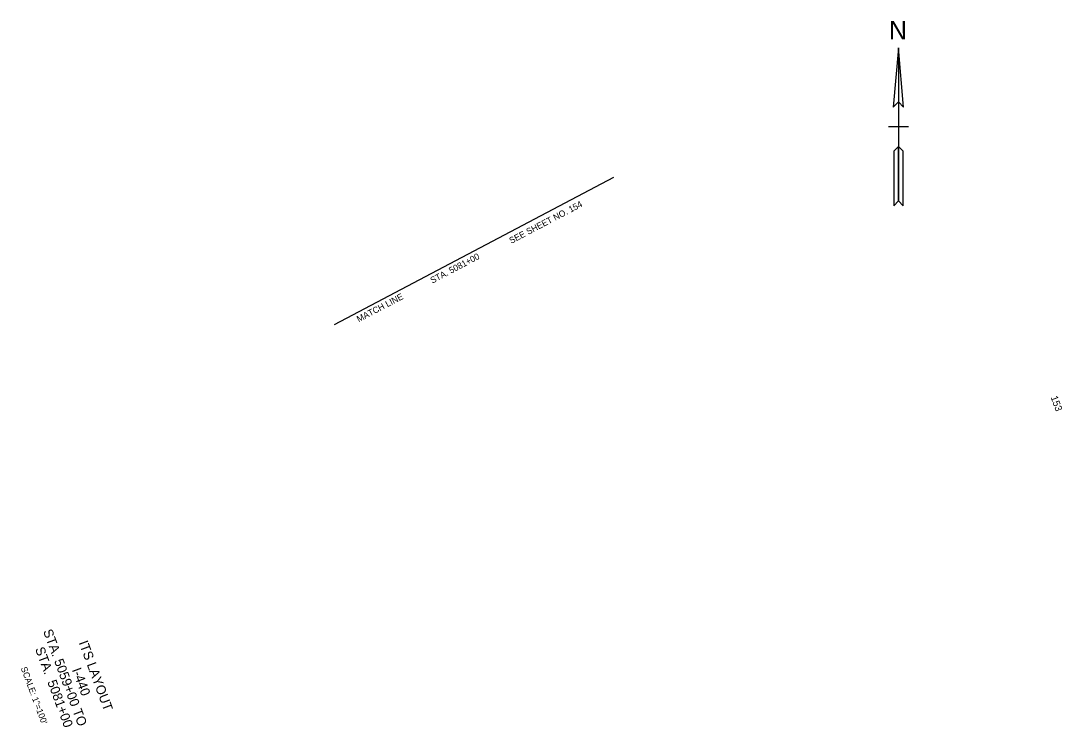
# Model space of a CAD drawing. Extents: x -200 to 1727510, y -325 to 658951.
# Drawn here: x 1725531 to 1727510, y 655994 to 657336 of the extents above; entities that cross this region are included whole.
import ezdxf

# ---------------------------------------------------------------- set-up
doc = ezdxf.new("R2010")
doc.units = 0
for name, color, linetype in [('DESIGN - CENTERLINE - Proposed Text', 7, 'Continuous'), ('DESIGN - SCRATCH - User 1', 7, 'Continuous'), ('DESIGN - SHEET - Corner Text', 7, 'Continuous'), ('ITS - CONST TEXT', 7, 'Continuous'), ('ITS - EXISITING WEATHER STATION', 7, 'Continuous'), ('ITS - EXISTING COMM CABLE', 7, 'Continuous'), ('ITS - EXISTING HAR', 7, 'Continuous')]:
    doc.layers.add(name, color=color, linetype=linetype)

msp = doc.modelspace()

# ---------------------------------------------------------------- linework, layer by layer
at = {"layer": 'DESIGN - CENTERLINE - Proposed Text'}
for p, q in [((1727198.5, 657134.9), (1727179.6, 657134.9)), ((1727217.4, 657134.9), (1727198.5, 657134.9))]:
    msp.add_line(p, q, dxfattribs=at)
msp.add_lwpolyline([(1727198.5, 657284.9), (1727188.7, 657172.3), (1727198.5, 657182.1), (1727208.3, 657172.3), (1727198.5, 657284.9), (1727198.5, 656994), (1727207.6, 656984.9), (1727207.6, 657088.4), (1727198.5, 657097.5), (1727189.4, 657088.4), (1727189.4, 656984.9), (1727198.5, 656994)], dxfattribs=at)
for points in [[(1727198.5, 657182.1), (1727208.3, 657172.3), (1727198.5, 657284.9)], [(1727189.4, 656984.9), (1727198.5, 656994), (1727198.5, 657097.5), (1727189.4, 657088.4)]]:
    msp.add_lwpolyline(points, close=True, dxfattribs=at)
at = {"layer": 'DESIGN - SCRATCH - User 1'}
for p, q in [((1725638.6, 656061.2), (1725638.6, 656061.2)), ((1725638.6, 656061.2), (1725638.6, 656061.2)), ((1725624.3, 656052.5), (1725624.3, 656052.5))]:
    msp.add_line(p, q, dxfattribs=at)
at = {"layer": 'ITS - EXISITING WEATHER STATION'}
msp.add_line((1725638.6, 656061.4), (1725638.6, 656061.4), dxfattribs=at)
msp.add_line((1725638.6, 656061.4), (1725638.6, 656061.4), dxfattribs=at)
at = {"layer": 'ITS - EXISTING COMM CABLE'}
msp.add_line((1726126.7, 656759.1), (1726657.5, 657038.9), dxfattribs=at)

# ---------------------------------------------------------------- texts
at = {"layer": 'DESIGN - CENTERLINE - Proposed Text'}
msp.add_text('N', height=35.4, dxfattribs=at).set_placement((1727180.4, 657301))
at = {"layer": 'DESIGN - SHEET - Corner Text'}
msp.add_text('153', height=13.5, rotation=290.3031, dxfattribs=at).set_placement((1727487.4, 656620.8))
at = {"layer": 'ITS - CONST TEXT'}
msp.add_text('SCALE: 1"=100\'', height=12, rotation=290.3032, dxfattribs=at).set_placement((1725530.3, 656106))
at = {"layer": 'ITS - EXISTING COMM CABLE'}
for s, p in [('SEE SHEET NO. 154 ', (1726462.6, 656912.2)), ('STA. 5081+00', (1726312.6, 656836.7)), ('MATCH LINE', (1726172.8, 656763.1))]:
    msp.add_text(s, height=12, rotation=27.7894, dxfattribs=at).set_placement(p)
at = {"layer": 'ITS - EXISTING HAR'}
for s, p in [('STA. 5059+00 TO', (1725572.7, 656176.1)), ('ITS LAYOUT', (1725640.4, 656154.3)), ('STA.  5081+00', (1725557.5, 656142.3)), ('I-440', (1725627.6, 656102.7))]:
    msp.add_text(s, height=18, rotation=290.3032, dxfattribs=at).set_placement(p)

doc.saveas('drawing.dxf')
